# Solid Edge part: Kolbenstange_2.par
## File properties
Username: bmolnar
Dokumentum tartalom típus: 0
Author: bmolnar
Last saved by: bmolnar
Revision: 97
Sűrűség: 0,000 kg/m^3
Pontosság: 0,990
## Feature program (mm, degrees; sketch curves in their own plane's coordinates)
base feature "unnamed BaseFeature 1"
thread "unnamed Thread 1"
chamfer "Letörés_1"  SetBackValue2 = 20 deg
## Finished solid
Body 1: solid body, 20 faces, 35 edges, 19 vertices.
  Faces by surface: plane 8, cylinder 5, torus 4, cone 3
  Edges by curve: circle 19, line 10, curve on surface 4, ellipse 2
Bounding box of the edges (mm; curved faces can reach further): 50.000 x 50.000 x 2901.000, from (-25, -25, -63.5) to (25, 25, 2837.5).
Cylindrical faces by radius (mm): R6.75 x1, R8 x1, R9.75 x1, R10 x1, R25 x1
Conical faces (half-angle, radius in mm at the cone's reference point): 20 deg R6.5004 x1, 30 deg R9.875 x1, 60 deg R7.375 x1
Toroidal faces (ring radius, tube radius in mm): R7.15 r0.4 x2, R8.55 r1.2 x2
Planar faces by outward normal: +x 1, +z 3, -x 1, -z 1, oblique 2
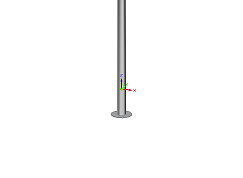
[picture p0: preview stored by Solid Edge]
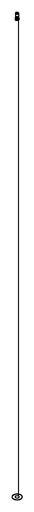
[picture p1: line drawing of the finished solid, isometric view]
